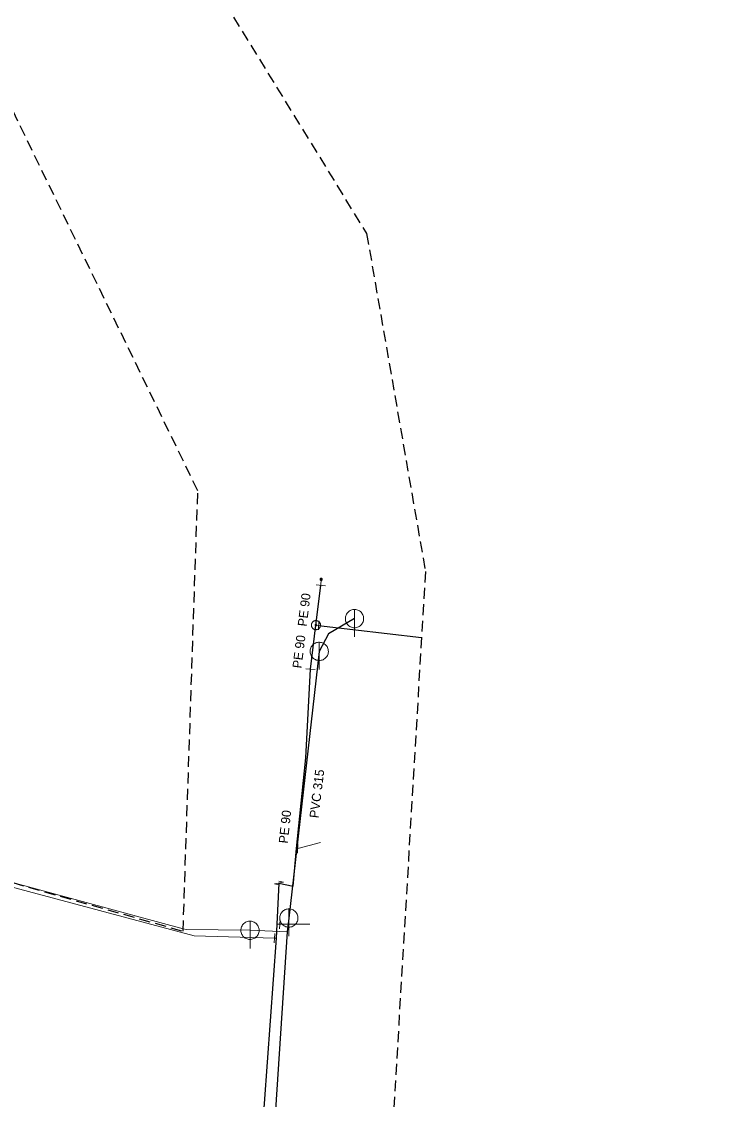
# Model space of a CAD drawing. Extents: x -686636 to -686482, y -972667 to -972167.
# Drawn here: x -686559.3 to -686482.1, y -972568.3 to -972450.3 of the extents above; entities that cross this region are included whole.
import ezdxf

# ---------------------------------------------------------------- set-up
doc = ezdxf.new("R2010")
doc.units = 0
doc.header["$LTSCALE"] = 0.4
doc.linetypes.add('MEDIUM_DASHED', pattern=[4.5, 3, -1.5])
for name, color, linetype, lineweight in [('1', 7, 'MEDIUM_DASHED', 25), ('11', 7, 'Continuous', 13), ('13', 7, 'Continuous', 13), ('14', 7, 'Continuous', 25), ('17', 7, 'Continuous', 25), ('22', 7, 'Continuous', 13), ('34', 7, 'Continuous', 13), ('47', 7, 'Continuous', 13), ('9', 7, 'Continuous', 13)]:
    doc.layers.add(name, color=color, linetype=linetype, lineweight=lineweight)

msp = doc.modelspace()

# ---------------------------------------------------------------- linework, layer by layer
at = {"layer": '1'}
msp.add_lwpolyline([(-686523.086, -972200.227), (-686492.539, -972167.269), (-686482.089, -972185.758), (-686542.379, -972270.164), (-686548.006, -972279.81), (-686543.183, -972295.084), (-686523.086, -972321.612), (-686521.478, -972360.197), (-686540.771, -972442.192), (-686521.478, -972473.543), (-686515.047, -972510.521), (-686519.067, -972578.85), (-686529.517, -972667.276), (-686549.614, -972665.668), (-686542.379, -972574.831), (-686589.003, -972562.773), (-686636.432, -972544.284), (-686625.981, -972525.795), (-686541.575, -972549.911), (-686539.967, -972501.678), (-686569.711, -972440.584), (-686549.614, -972329.65), (-686564.887, -972297.496), (-686572.926, -972277.399)], close=True, dxfattribs=at)
at = {"layer": '11'}
msp.add_line((-686534.25, -972549.8), (-686530.171, -972549.975), dxfattribs=at)
msp.add_lwpolyline([(-686589.202, -972536.303), (-686589.197, -972536.741), (-686560.251, -972544.575), (-686541.566, -972549.631), (-686541.243, -972549.719), (-686534.25, -972549.8)], dxfattribs=at)
at = {"layer": '13'}
for p, q in [((-686529.02, -972540.84), (-686526.53, -972540.199)), ((-686530.997, -972549.142), (-686527.687, -972549.122)), ((-686531.579, -972550.66), (-686540.37, -972550.399))]:
    msp.add_line(p, q, dxfattribs=at)
msp.add_lwpolyline([(-686540.37, -972550.399), (-686589.62, -972537.239), (-686589.61, -972536.187)], dxfattribs=at)
at = {"layer": '14', "lineweight": 13}
for p, q in [((-686526.5, -972512.05), (-686526.46, -972511.379)), ((-686527.032, -972516.396), (-686526.739, -972516.42)), ((-686529.174, -972540.836), (-686529.02, -972540.84)), ((-686531.317, -972549.123), (-686530.997, -972549.142)), ((-686531.386, -972550.671), (-686531.579, -972550.66))]:
    msp.add_line(p, q, dxfattribs=at)
at = {"layer": '14'}
msp.add_line((-686526.67, -972519.27), (-686529.998, -972548.457), dxfattribs=at)
for points in [[(-686522.809, -972515.68), (-686525.649, -972517.34), (-686526.67, -972519.27)], [(-686529.998, -972548.457), (-686530.171, -972549.975), (-686536.5, -972646.26)]]:
    msp.add_lwpolyline(points, dxfattribs=at)
at = {"layer": '17'}
for p, q in [((-686527.032, -972516.396), (-686526.5, -972512.05)), ((-686527.629, -972521.219), (-686527.032, -972516.396)), ((-686526.739, -972516.42), (-686515.473, -972517.755))]:
    msp.add_line(p, q, dxfattribs=at)
for points in [[(-686531.079, -972544.64), (-686529.52, -972544.969), (-686529.174, -972540.836), (-686528.149, -972530.92), (-686527.629, -972521.219)], [(-686531.079, -972544.64), (-686531.317, -972549.123), (-686531.386, -972550.671), (-686534.66, -972595.9)]]:
    msp.add_lwpolyline(points, dxfattribs=at)
at = {"layer": '22'}
for p, q in [((-686522.809, -972517.68), (-686522.808, -972514.68)), ((-686526.67, -972521.27), (-686526.669, -972518.27)), ((-686529.998, -972550.457), (-686529.997, -972547.457)), ((-686534.25, -972551.8), (-686534.249, -972548.8))]:
    msp.add_line(p, q, dxfattribs=at)
for points in [[(-686521.809, -972515.68), (-686521.814, -972515.571), (-686521.832, -972515.463), (-686521.862, -972515.357), (-686521.902, -972515.256), (-686521.954, -972515.159), (-686522.016, -972515.069), (-686522.088, -972514.986), (-686522.168, -972514.912), (-686522.256, -972514.846), (-686522.35, -972514.791), (-686522.45, -972514.746), (-686522.555, -972514.713), (-686522.662, -972514.691), (-686522.771, -972514.681), (-686522.881, -972514.683), (-686522.989, -972514.697), (-686523.096, -972514.722), (-686523.199, -972514.759), (-686523.297, -972514.808), (-686523.389, -972514.866), (-686523.475, -972514.935), (-686523.552, -972515.012), (-686523.621, -972515.098), (-686523.68, -972515.19), (-686523.728, -972515.288), (-686523.765, -972515.391), (-686523.791, -972515.498), (-686523.805, -972515.606), (-686523.808, -972515.716), (-686523.798, -972515.825), (-686523.777, -972515.932), (-686523.743, -972516.036), (-686523.699, -972516.136), (-686523.644, -972516.231), (-686523.578, -972516.319), (-686523.504, -972516.399), (-686523.421, -972516.471), (-686523.331, -972516.533), (-686523.235, -972516.585), (-686523.133, -972516.626), (-686523.028, -972516.656), (-686522.92, -972516.674), (-686522.81, -972516.68), (-686522.701, -972516.674), (-686522.593, -972516.656), (-686522.488, -972516.627), (-686522.386, -972516.586), (-686522.289, -972516.534), (-686522.199, -972516.472), (-686522.116, -972516.401), (-686522.041, -972516.321), (-686521.976, -972516.233), (-686521.92, -972516.139), (-686521.876, -972516.039), (-686521.842, -972515.935), (-686521.82, -972515.827), (-686521.81, -972515.718)], [(-686525.67, -972519.27), (-686525.675, -972519.161), (-686525.693, -972519.053), (-686525.723, -972518.947), (-686525.763, -972518.846), (-686525.815, -972518.749), (-686525.877, -972518.659), (-686525.949, -972518.576), (-686526.029, -972518.502), (-686526.117, -972518.436), (-686526.211, -972518.381), (-686526.311, -972518.336), (-686526.416, -972518.303), (-686526.523, -972518.281), (-686526.632, -972518.271), (-686526.742, -972518.273), (-686526.85, -972518.287), (-686526.957, -972518.312), (-686527.06, -972518.349), (-686527.158, -972518.398), (-686527.25, -972518.456), (-686527.336, -972518.525), (-686527.413, -972518.602), (-686527.482, -972518.688), (-686527.541, -972518.78), (-686527.589, -972518.878), (-686527.626, -972518.981), (-686527.652, -972519.088), (-686527.666, -972519.196), (-686527.669, -972519.306), (-686527.659, -972519.415), (-686527.638, -972519.522), (-686527.604, -972519.626), (-686527.56, -972519.726), (-686527.505, -972519.821), (-686527.439, -972519.909), (-686527.365, -972519.989), (-686527.282, -972520.061), (-686527.192, -972520.123), (-686527.096, -972520.175), (-686526.994, -972520.216), (-686526.889, -972520.246), (-686526.781, -972520.264), (-686526.671, -972520.27), (-686526.562, -972520.264), (-686526.454, -972520.246), (-686526.349, -972520.217), (-686526.247, -972520.176), (-686526.15, -972520.124), (-686526.06, -972520.062), (-686525.977, -972519.991), (-686525.902, -972519.911), (-686525.837, -972519.823), (-686525.781, -972519.729), (-686525.737, -972519.629), (-686525.703, -972519.525), (-686525.681, -972519.417), (-686525.671, -972519.308)], [(-686528.998, -972548.457), (-686529.003, -972548.348), (-686529.021, -972548.24), (-686529.051, -972548.134), (-686529.091, -972548.033), (-686529.143, -972547.936), (-686529.205, -972547.846), (-686529.277, -972547.763), (-686529.357, -972547.689), (-686529.445, -972547.623), (-686529.539, -972547.568), (-686529.639, -972547.523), (-686529.744, -972547.49), (-686529.851, -972547.468), (-686529.96, -972547.458), (-686530.07, -972547.46), (-686530.178, -972547.474), (-686530.285, -972547.499), (-686530.388, -972547.536), (-686530.486, -972547.585), (-686530.578, -972547.643), (-686530.664, -972547.712), (-686530.741, -972547.789), (-686530.81, -972547.875), (-686530.869, -972547.967), (-686530.917, -972548.065), (-686530.954, -972548.168), (-686530.98, -972548.275), (-686530.994, -972548.383), (-686530.997, -972548.493), (-686530.987, -972548.602), (-686530.966, -972548.709), (-686530.932, -972548.813), (-686530.888, -972548.913), (-686530.833, -972549.008), (-686530.767, -972549.096), (-686530.693, -972549.176), (-686530.61, -972549.248), (-686530.52, -972549.31), (-686530.424, -972549.362), (-686530.322, -972549.403), (-686530.217, -972549.433), (-686530.109, -972549.451), (-686529.999, -972549.457), (-686529.89, -972549.451), (-686529.782, -972549.433), (-686529.677, -972549.404), (-686529.575, -972549.363), (-686529.478, -972549.311), (-686529.388, -972549.249), (-686529.305, -972549.178), (-686529.23, -972549.098), (-686529.165, -972549.01), (-686529.109, -972548.916), (-686529.065, -972548.816), (-686529.031, -972548.712), (-686529.009, -972548.604), (-686528.999, -972548.495)], [(-686533.25, -972549.8), (-686533.255, -972549.691), (-686533.273, -972549.583), (-686533.303, -972549.477), (-686533.343, -972549.376), (-686533.395, -972549.279), (-686533.457, -972549.189), (-686533.529, -972549.106), (-686533.609, -972549.032), (-686533.697, -972548.966), (-686533.791, -972548.911), (-686533.891, -972548.866), (-686533.996, -972548.833), (-686534.103, -972548.811), (-686534.212, -972548.801), (-686534.322, -972548.803), (-686534.43, -972548.817), (-686534.537, -972548.842), (-686534.64, -972548.879), (-686534.738, -972548.928), (-686534.83, -972548.986), (-686534.916, -972549.055), (-686534.993, -972549.132), (-686535.062, -972549.218), (-686535.121, -972549.31), (-686535.169, -972549.408), (-686535.206, -972549.511), (-686535.232, -972549.618), (-686535.246, -972549.726), (-686535.249, -972549.836), (-686535.239, -972549.945), (-686535.218, -972550.052), (-686535.184, -972550.156), (-686535.14, -972550.256), (-686535.085, -972550.351), (-686535.019, -972550.439), (-686534.945, -972550.519), (-686534.862, -972550.591), (-686534.772, -972550.653), (-686534.676, -972550.705), (-686534.574, -972550.746), (-686534.469, -972550.776), (-686534.361, -972550.794), (-686534.251, -972550.8), (-686534.142, -972550.794), (-686534.034, -972550.776), (-686533.929, -972550.747), (-686533.827, -972550.706), (-686533.73, -972550.654), (-686533.64, -972550.592), (-686533.557, -972550.521), (-686533.482, -972550.441), (-686533.417, -972550.353), (-686533.361, -972550.259), (-686533.317, -972550.159), (-686533.283, -972550.055), (-686533.261, -972549.947), (-686533.251, -972549.838)]]:
    msp.add_lwpolyline(points, close=True, dxfattribs=at)
at = {"layer": '34'}
for p, q in [((-686526.997, -972512.001), (-686526.002, -972512.099)), ((-686526.723, -972515.92), (-686526.755, -972516.919)), ((-686528.128, -972521.189), (-686527.129, -972521.249)), ((-686529.008, -972540.34), (-686529.032, -972541.339)), ((-686530.959, -972548.643), (-686531.035, -972549.64)), ((-686531.609, -972551.159), (-686531.547, -972550.16))]:
    msp.add_line(p, q, dxfattribs=at)
at = {"layer": '47'}
msp.add_line((-686530.577, -972544.549), (-686531.076, -972544.439), dxfattribs=at)
for points in [[(-686527.007, -972515.896), (-686527.059, -972515.897), (-686527.111, -972515.902), (-686527.162, -972515.913), (-686527.212, -972515.929), (-686527.26, -972515.951), (-686527.305, -972515.978), (-686527.347, -972516.009), (-686527.386, -972516.044), (-686527.421, -972516.082), (-686527.452, -972516.124), (-686527.478, -972516.17), (-686527.498, -972516.218), (-686527.515, -972516.268), (-686527.525, -972516.319), (-686527.531, -972516.371), (-686527.53, -972516.423), (-686527.525, -972516.475), (-686527.514, -972516.527), (-686527.498, -972516.576), (-686527.476, -972516.624), (-686527.449, -972516.669), (-686527.419, -972516.712), (-686527.383, -972516.751), (-686527.345, -972516.786), (-686527.303, -972516.816), (-686527.257, -972516.842), (-686527.209, -972516.863), (-686527.159, -972516.879), (-686527.108, -972516.889), (-686527.056, -972516.895), (-686527.004, -972516.894), (-686526.952, -972516.889), (-686526.9, -972516.879), (-686526.851, -972516.862), (-686526.803, -972516.84), (-686526.758, -972516.814), (-686526.715, -972516.784), (-686526.676, -972516.748), (-686526.641, -972516.709), (-686526.611, -972516.667), (-686526.585, -972516.621), (-686526.564, -972516.574), (-686526.548, -972516.523), (-686526.538, -972516.472), (-686526.532, -972516.42), (-686526.533, -972516.368), (-686526.538, -972516.316), (-686526.548, -972516.265), (-686526.565, -972516.215), (-686526.587, -972516.167), (-686526.613, -972516.122), (-686526.644, -972516.08), (-686526.679, -972516.041), (-686526.718, -972516.006), (-686526.76, -972515.975), (-686526.806, -972515.949), (-686526.853, -972515.929), (-686526.904, -972515.912), (-686526.955, -972515.902)], [(-686527.027, -972516.314), (-686527.036, -972516.313), (-686527.045, -972516.315), (-686527.053, -972516.316), (-686527.061, -972516.319), (-686527.069, -972516.323), (-686527.076, -972516.327), (-686527.083, -972516.332), (-686527.09, -972516.338), (-686527.095, -972516.344), (-686527.1, -972516.351), (-686527.105, -972516.359), (-686527.108, -972516.367), (-686527.111, -972516.375), (-686527.113, -972516.382), (-686527.113, -972516.391), (-686527.114, -972516.4), (-686527.112, -972516.409), (-686527.111, -972516.417), (-686527.108, -972516.425), (-686527.104, -972516.433), (-686527.1, -972516.44), (-686527.095, -972516.447), (-686527.089, -972516.454), (-686527.083, -972516.46), (-686527.076, -972516.464), (-686527.068, -972516.469), (-686527.06, -972516.472), (-686527.052, -972516.475), (-686527.045, -972516.477), (-686527.036, -972516.477), (-686527.027, -972516.478), (-686527.018, -972516.476), (-686527.01, -972516.475), (-686527.002, -972516.472), (-686526.994, -972516.468), (-686526.987, -972516.465), (-686526.98, -972516.459), (-686526.973, -972516.453), (-686526.967, -972516.447), (-686526.963, -972516.44), (-686526.958, -972516.432), (-686526.955, -972516.424), (-686526.952, -972516.416), (-686526.95, -972516.409), (-686526.95, -972516.4), (-686526.949, -972516.391), (-686526.951, -972516.382), (-686526.952, -972516.374), (-686526.955, -972516.366), (-686526.959, -972516.358), (-686526.962, -972516.351), (-686526.968, -972516.344), (-686526.974, -972516.337), (-686526.98, -972516.332), (-686526.987, -972516.327), (-686526.995, -972516.322), (-686527.003, -972516.319), (-686527.011, -972516.316), (-686527.018, -972516.314)]]:
    msp.add_lwpolyline(points, close=True, dxfattribs=at)
msp.add_lwpolyline([(-686530.577, -972544.549), (-686531.58, -972544.73), (-686531.081, -972544.84)], dxfattribs=at)
at = {"layer": '9'}
for points in [[(-686526.586, -972511.379), (-686526.586, -972511.392), (-686526.583, -972511.405), (-686526.581, -972511.418), (-686526.576, -972511.43), (-686526.57, -972511.442), (-686526.563, -972511.453), (-686526.554, -972511.463), (-686526.544, -972511.473), (-686526.534, -972511.481), (-686526.524, -972511.488), (-686526.512, -972511.494), (-686526.5, -972511.499), (-686526.487, -972511.502), (-686526.473, -972511.504), (-686526.461, -972511.506), (-686526.448, -972511.505), (-686526.434, -972511.503), (-686526.422, -972511.5), (-686526.409, -972511.495), (-686526.397, -972511.489), (-686526.387, -972511.482), (-686526.377, -972511.474), (-686526.367, -972511.464), (-686526.358, -972511.454), (-686526.352, -972511.443), (-686526.346, -972511.431), (-686526.341, -972511.419), (-686526.338, -972511.406), (-686526.336, -972511.393), (-686526.333, -972511.38), (-686526.335, -972511.367), (-686526.337, -972511.354), (-686526.34, -972511.341), (-686526.345, -972511.329), (-686526.35, -972511.317), (-686526.358, -972511.306), (-686526.365, -972511.296), (-686526.375, -972511.286), (-686526.386, -972511.278), (-686526.397, -972511.271), (-686526.409, -972511.265), (-686526.421, -972511.26), (-686526.434, -972511.257), (-686526.446, -972511.255), (-686526.46, -972511.254), (-686526.473, -972511.254), (-686526.485, -972511.256), (-686526.499, -972511.259), (-686526.511, -972511.264), (-686526.522, -972511.27), (-686526.534, -972511.277), (-686526.544, -972511.285), (-686526.554, -972511.295), (-686526.561, -972511.305), (-686526.569, -972511.316), (-686526.575, -972511.328), (-686526.58, -972511.34), (-686526.583, -972511.353), (-686526.585, -972511.366)], [(-686526.566, -972511.379), (-686526.566, -972511.39), (-686526.565, -972511.401), (-686526.561, -972511.412), (-686526.558, -972511.422), (-686526.553, -972511.432), (-686526.547, -972511.441), (-686526.539, -972511.45), (-686526.532, -972511.458), (-686526.522, -972511.465), (-686526.514, -972511.471), (-686526.504, -972511.476), (-686526.494, -972511.48), (-686526.483, -972511.483), (-686526.472, -972511.486), (-686526.461, -972511.486), (-686526.45, -972511.486), (-686526.439, -972511.484), (-686526.428, -972511.481), (-686526.418, -972511.477), (-686526.407, -972511.472), (-686526.399, -972511.466), (-686526.39, -972511.459), (-686526.382, -972511.451), (-686526.375, -972511.442), (-686526.369, -972511.433), (-686526.364, -972511.423), (-686526.36, -972511.413), (-686526.357, -972511.402), (-686526.355, -972511.391), (-686526.353, -972511.38), (-686526.353, -972511.369), (-686526.355, -972511.358), (-686526.358, -972511.347), (-686526.363, -972511.337), (-686526.368, -972511.327), (-686526.374, -972511.318), (-686526.38, -972511.309), (-686526.389, -972511.301), (-686526.397, -972511.294), (-686526.407, -972511.288), (-686526.417, -972511.283), (-686526.426, -972511.279), (-686526.438, -972511.276), (-686526.448, -972511.274), (-686526.46, -972511.274), (-686526.471, -972511.273), (-686526.482, -972511.275), (-686526.493, -972511.278), (-686526.502, -972511.282), (-686526.512, -972511.287), (-686526.522, -972511.293), (-686526.531, -972511.3), (-686526.539, -972511.308), (-686526.546, -972511.317), (-686526.551, -972511.326), (-686526.556, -972511.336), (-686526.561, -972511.346), (-686526.564, -972511.357), (-686526.566, -972511.368)], [(-686526.547, -972511.379), (-686526.547, -972511.388), (-686526.546, -972511.397), (-686526.543, -972511.406), (-686526.539, -972511.414), (-686526.536, -972511.422), (-686526.531, -972511.43), (-686526.524, -972511.437), (-686526.519, -972511.443), (-686526.512, -972511.449), (-686526.504, -972511.454), (-686526.495, -972511.458), (-686526.488, -972511.461), (-686526.478, -972511.464), (-686526.47, -972511.465), (-686526.461, -972511.467), (-686526.451, -972511.466), (-686526.443, -972511.465), (-686526.434, -972511.462), (-686526.426, -972511.459), (-686526.418, -972511.455), (-686526.409, -972511.45), (-686526.402, -972511.444), (-686526.397, -972511.438), (-686526.391, -972511.431), (-686526.386, -972511.423), (-686526.382, -972511.415), (-686526.379, -972511.407), (-686526.375, -972511.398), (-686526.375, -972511.389), (-686526.372, -972511.38), (-686526.374, -972511.371), (-686526.375, -972511.362), (-686526.377, -972511.353), (-686526.38, -972511.345), (-686526.385, -972511.337), (-686526.39, -972511.329), (-686526.396, -972511.322), (-686526.402, -972511.316), (-686526.409, -972511.31), (-686526.417, -972511.305), (-686526.424, -972511.301), (-686526.433, -972511.298), (-686526.441, -972511.295), (-686526.451, -972511.294), (-686526.46, -972511.293), (-686526.468, -972511.293), (-686526.478, -972511.294), (-686526.487, -972511.297), (-686526.495, -972511.3), (-686526.502, -972511.304), (-686526.511, -972511.309), (-686526.517, -972511.315), (-686526.524, -972511.321), (-686526.529, -972511.328), (-686526.534, -972511.336), (-686526.539, -972511.344), (-686526.542, -972511.352), (-686526.544, -972511.361), (-686526.546, -972511.37)], [(-686526.527, -972511.379), (-686526.527, -972511.386), (-686526.526, -972511.393), (-686526.524, -972511.4), (-686526.522, -972511.406), (-686526.519, -972511.412), (-686526.515, -972511.418), (-686526.511, -972511.424), (-686526.505, -972511.429), (-686526.5, -972511.433), (-686526.494, -972511.437), (-686526.488, -972511.44), (-686526.482, -972511.443), (-686526.475, -972511.444), (-686526.468, -972511.447), (-686526.461, -972511.447), (-686526.453, -972511.447), (-686526.446, -972511.445), (-686526.44, -972511.444), (-686526.434, -972511.441), (-686526.426, -972511.438), (-686526.422, -972511.434), (-686526.416, -972511.43), (-686526.411, -972511.425), (-686526.407, -972511.419), (-686526.402, -972511.413), (-686526.399, -972511.407), (-686526.397, -972511.401), (-686526.395, -972511.394), (-686526.394, -972511.387), (-686526.392, -972511.38), (-686526.392, -972511.373), (-686526.394, -972511.366), (-686526.396, -972511.359), (-686526.399, -972511.353), (-686526.402, -972511.346), (-686526.406, -972511.341), (-686526.409, -972511.335), (-686526.414, -972511.33), (-686526.421, -972511.326), (-686526.426, -972511.322), (-686526.433, -972511.319), (-686526.439, -972511.316), (-686526.446, -972511.314), (-686526.453, -972511.313), (-686526.46, -972511.313), (-686526.467, -972511.313), (-686526.473, -972511.313), (-686526.48, -972511.315), (-686526.487, -972511.318), (-686526.493, -972511.321), (-686526.499, -972511.325), (-686526.505, -972511.329), (-686526.51, -972511.334), (-686526.514, -972511.34), (-686526.517, -972511.345), (-686526.521, -972511.352), (-686526.524, -972511.358), (-686526.524, -972511.365), (-686526.527, -972511.372)], [(-686526.507, -972511.379), (-686526.507, -972511.384), (-686526.507, -972511.389), (-686526.505, -972511.394), (-686526.504, -972511.398), (-686526.502, -972511.403), (-686526.499, -972511.407), (-686526.495, -972511.41), (-686526.492, -972511.414), (-686526.489, -972511.417), (-686526.485, -972511.42), (-686526.48, -972511.422), (-686526.475, -972511.424), (-686526.471, -972511.425), (-686526.466, -972511.427), (-686526.461, -972511.427), (-686526.456, -972511.427), (-686526.451, -972511.426), (-686526.446, -972511.425), (-686526.441, -972511.423), (-686526.436, -972511.421), (-686526.433, -972511.418), (-686526.429, -972511.415), (-686526.426, -972511.411), (-686526.423, -972511.408), (-686526.419, -972511.404), (-686526.418, -972511.399), (-686526.416, -972511.395), (-686526.414, -972511.39), (-686526.414, -972511.385), (-686526.413, -972511.38), (-686526.413, -972511.375), (-686526.414, -972511.37), (-686526.414, -972511.365), (-686526.417, -972511.361), (-686526.419, -972511.356), (-686526.422, -972511.352), (-686526.424, -972511.348), (-686526.428, -972511.345), (-686526.431, -972511.342), (-686526.436, -972511.339), (-686526.441, -972511.337), (-686526.445, -972511.335), (-686526.45, -972511.334), (-686526.455, -972511.333), (-686526.46, -972511.333), (-686526.465, -972511.333), (-686526.47, -972511.334), (-686526.475, -972511.334), (-686526.478, -972511.336), (-686526.483, -972511.338), (-686526.488, -972511.341), (-686526.49, -972511.344), (-686526.495, -972511.347), (-686526.497, -972511.351), (-686526.5, -972511.355), (-686526.502, -972511.36), (-686526.505, -972511.364), (-686526.505, -972511.369), (-686526.507, -972511.374)], [(-686526.487, -972511.379), (-686526.487, -972511.382), (-686526.488, -972511.385), (-686526.487, -972511.387), (-686526.485, -972511.39), (-686526.485, -972511.393), (-686526.483, -972511.395), (-686526.48, -972511.397), (-686526.478, -972511.399), (-686526.477, -972511.401), (-686526.475, -972511.403), (-686526.472, -972511.405), (-686526.468, -972511.406), (-686526.467, -972511.406), (-686526.463, -972511.407), (-686526.461, -972511.407), (-686526.458, -972511.407), (-686526.455, -972511.407), (-686526.451, -972511.406), (-686526.45, -972511.405), (-686526.446, -972511.404), (-686526.445, -972511.402), (-686526.441, -972511.4), (-686526.44, -972511.398), (-686526.439, -972511.396), (-686526.436, -972511.394), (-686526.436, -972511.391), (-686526.434, -972511.388), (-686526.434, -972511.386), (-686526.433, -972511.383), (-686526.431, -972511.38), (-686526.433, -972511.377), (-686526.433, -972511.374), (-686526.434, -972511.371), (-686526.434, -972511.369), (-686526.436, -972511.366), (-686526.438, -972511.364), (-686526.439, -972511.361), (-686526.441, -972511.359), (-686526.444, -972511.358), (-686526.446, -972511.356), (-686526.448, -972511.355), (-686526.451, -972511.354), (-686526.453, -972511.353), (-686526.456, -972511.353), (-686526.46, -972511.352), (-686526.463, -972511.353), (-686526.466, -972511.352), (-686526.468, -972511.354), (-686526.471, -972511.354), (-686526.473, -972511.355), (-686526.475, -972511.357), (-686526.478, -972511.358), (-686526.48, -972511.36), (-686526.482, -972511.363), (-686526.483, -972511.365), (-686526.485, -972511.368), (-686526.485, -972511.37), (-686526.487, -972511.373), (-686526.487, -972511.376)], [(-686526.468, -972511.379), (-686526.468, -972511.381), (-686526.468, -972511.381), (-686526.467, -972511.381), (-686526.467, -972511.383), (-686526.468, -972511.384), (-686526.466, -972511.384), (-686526.466, -972511.384), (-686526.466, -972511.386), (-686526.466, -972511.386), (-686526.465, -972511.387), (-686526.463, -972511.387), (-686526.463, -972511.387), (-686526.463, -972511.388), (-686526.461, -972511.388), (-686526.461, -972511.388), (-686526.46, -972511.388), (-686526.458, -972511.388), (-686526.458, -972511.387), (-686526.458, -972511.387), (-686526.456, -972511.387), (-686526.456, -972511.386), (-686526.456, -972511.386), (-686526.455, -972511.385), (-686526.455, -972511.385), (-686526.453, -972511.384), (-686526.453, -972511.383), (-686526.451, -972511.382), (-686526.451, -972511.382), (-686526.451, -972511.381), (-686526.451, -972511.38), (-686526.451, -972511.379), (-686526.451, -972511.378), (-686526.451, -972511.378), (-686526.453, -972511.377), (-686526.453, -972511.376), (-686526.453, -972511.375), (-686526.453, -972511.375), (-686526.455, -972511.374), (-686526.455, -972511.374), (-686526.456, -972511.373), (-686526.456, -972511.373), (-686526.458, -972511.372), (-686526.458, -972511.372), (-686526.458, -972511.372), (-686526.46, -972511.372), (-686526.461, -972511.372), (-686526.462, -972511.372), (-686526.462, -972511.372), (-686526.463, -972511.373), (-686526.463, -972511.372), (-686526.465, -972511.374), (-686526.465, -972511.374), (-686526.466, -972511.374), (-686526.466, -972511.374), (-686526.467, -972511.376), (-686526.467, -972511.377), (-686526.467, -972511.378), (-686526.468, -972511.378), (-686526.468, -972511.379)]]:
    msp.add_lwpolyline(points, close=True, dxfattribs=at)

# ---------------------------------------------------------------- texts
at = {"layer": '1'}
for s, rotation, p in [('PE 90 ', 83, (-686528.047, -972516.584)), ('PE 90 ', 83, (-686528.615, -972521.167)), ('PVC 315 ', 83, (-686526.757, -972537.566)), ('PE 90 ', 84, (-686530.114, -972540.331))]:
    msp.add_text(s, height=1, rotation=rotation, dxfattribs=at).set_placement(p)

doc.saveas('drawing.dxf')
